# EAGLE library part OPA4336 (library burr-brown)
Single-Supply, MicroPower CMOS Operational Amplifiers MicroAmplifier (TM) Series
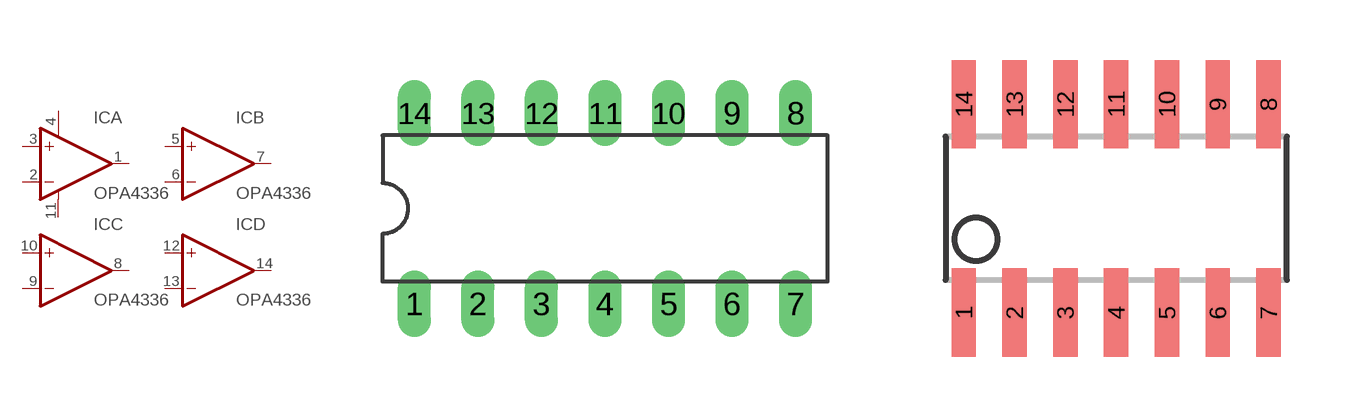
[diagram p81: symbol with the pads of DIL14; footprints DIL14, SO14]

Designator prefix IC; gates A=OP-AMP+- B=OP-AMP C=OP-AMP D=OP-AMP

## OPA4336P (OC_FARNELL: unknown; OC_NEWARK: unknown)  [DIL14]
1  A:OUT  out
2  A:-IN  in
3  A:+IN  in
4  A:V+  pwr
5  B:+IN  in
6  B:-IN  in
7  B:OUT  out
8  C:OUT  out
9  C:-IN  in
10  C:+IN  in
11  A:V-  pwr
12  D:+IN  in
13  D:-IN  in
14  D:OUT  out

## OPA4336U (OC_FARNELL: unknown; OC_NEWARK: unknown)  [SO14]
Pads as for DIL14

## OPA4336E (MF: TEXAS INSTRUMENTS; MPN: OPA4336EA/250; OC_FARNELL: 1207060; OC_NEWARK: 74K3911)  [SSOP16BU]
1  A:OUT  out
2  A:-IN  in
3  A:+IN  in
4  A:V+  pwr
5  B:+IN  in
6  B:-IN  in
7  B:OUT  out
10  C:OUT  out
11  C:-IN  in
12  C:+IN  in
13  A:V-  pwr
14  D:+IN  in
15  D:-IN  in
16  D:OUT  out

## Footprint DIL14 (pad centres in mm)
Dual In Line Package
drill 0.813 long: 1 -7.62,-3.81; 2 -5.08,-3.81; 3 -2.54,-3.81; 4 0,-3.81; 5 2.54,-3.81; 6 5.08,-3.81; 7 7.62,-3.81; 8 7.62,3.81; 9 5.08,3.81; 10 2.54,3.81; 11 0,3.81; 12 -2.54,3.81; 13 -5.08,3.81; 14 -7.62,3.81

## Footprint SO14 (pad centres in mm)
Small Outline Package
smd 0.61 x 2.21: 1 -3.81,-2.603; 2 -2.54,-2.603; 3 -1.27,-2.603; 4 0,-2.603; 5 1.27,-2.603; 6 2.54,-2.603; 7 3.81,-2.603; 8 3.81,2.603; 9 2.54,2.603; 10 1.27,2.603; 11 0,2.603; 12 -1.27,2.603; 13 -2.54,2.603; 14 -3.81,2.603

## Footprint SSOP16BU (pad centres in mm)
Small Shrink Outline Package Source: http://focus.ti.com/lit/ml/msoi004e/msoi004e.pdf
smd 0.348 x 1.397: 1 -2.223,-2.619; 2 -1.588,-2.62; 3 -0.953,-2.62; 4 -0.318,-2.62; 5 0.318,-2.62; 6 0.953,-2.62; 7 1.588,-2.62; 8 2.223,-2.62; 9 2.223,2.62; 10 1.588,2.62; 11 0.953,2.62; 12 0.318,2.62; 13 -0.318,2.62; 14 -0.953,2.62; 15 -1.588,2.62; 16 -2.223,2.62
